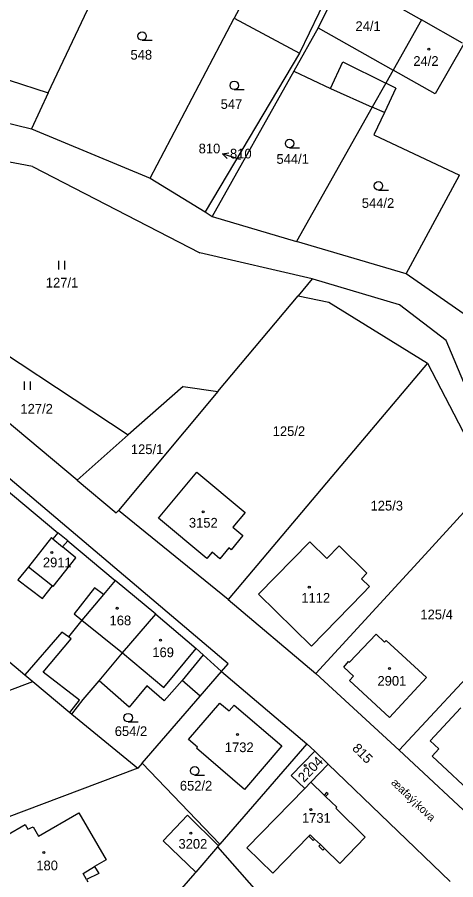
# Model space of a CAD drawing. Extents: x -735249 to -729401, y -1124843 to -1121828.
# Drawn here: x -734491.8 to -734414.9, y -1123251.2 to -1123099.8 of the extents above; entities that cross this region are included whole.
import ezdxf

# ---------------------------------------------------------------- set-up
doc = ezdxf.new("R2010")
doc.units = 0
for name, color, linetype in [('Vrstva 1', 7, 'Continuous'), ('Vrstva 15', 7, 'Continuous'), ('Vrstva 16', 7, 'Continuous'), ('Vrstva 18', 7, 'Continuous'), ('Vrstva 19', 7, 'Continuous'), ('Vrstva 25', 7, 'Continuous'), ('Vrstva 4', 7, 'Continuous')]:
    doc.layers.add(name, color=color, linetype=linetype)

msp = doc.modelspace()

# ---------------------------------------------------------------- linework, layer by layer
at = {"layer": 'Vrstva 1'}
for points in [[(-734486.39, -1123113.07), (-734474.7, -1123088.32)], [(-734435.54, -1123092.02), (-734442.31, -1123106.14)], [(-734434.51, -1123092.58), (-734439.06, -1123101.69)], [(-734434.51, -1123092.58), (-734420.91, -1123100.29)], [(-734452.51, -1123097.58), (-734453.76, -1123099.97)], [(-734468.49, -1123128.05), (-734453.76, -1123099.97)], [(-734453.76, -1123099.97), (-734442.31, -1123106.14)], [(-734439.06, -1123101.69), (-734443.32, -1123109.26)], [(-734420.91, -1123100.29), (-734425.89, -1123109.1)], [(-734413.69, -1123104.39), (-734420.91, -1123100.29)], [(-734442.31, -1123106.14), (-734458.84, -1123133.95)], [(-734500.17, -1123108.63), (-734486.39, -1123113.07)], [(-734443.32, -1123109.26), (-734457.65, -1123134.79)], [(-734443.32, -1123109.26), (-734436.89, -1123112.35)], [(-734425.89, -1123109.1), (-734427.19, -1123111.4)], [(-734427.19, -1123111.4), (-734429.54, -1123115.57)], [(-734486.39, -1123113.07), (-734489.33, -1123119.37)], [(-734436.89, -1123112.35), (-734429.54, -1123115.57)], [(-734504.01, -1123115.82), (-734489.33, -1123119.37)], [(-734429.54, -1123115.57), (-734442.85, -1123139.15)], [(-734427.4, -1123116.52), (-734429.54, -1123115.57)], [(-734427.4, -1123116.52), (-734429.27, -1123120.47)], [(-734489.33, -1123119.37), (-734468.49, -1123128.05)], [(-734429.27, -1123120.47), (-734414.25, -1123127.53)], [(-734489.13, -1123126), (-734505.01, -1123123.05)], [(-734489.13, -1123126), (-734459.78, -1123141.16)], [(-734468.49, -1123128.05), (-734458.84, -1123133.95)], [(-734423.62, -1123144.82), (-734414.25, -1123127.53)], [(-734458.84, -1123133.95), (-734457.65, -1123134.79)], [(-734457.65, -1123134.79), (-734442.85, -1123139.15)], [(-734423.62, -1123144.82), (-734442.85, -1123139.15)], [(-734440.1, -1123145.74), (-734459.78, -1123141.16)], [(-734412.28, -1123152.75), (-734423.62, -1123144.82)], [(-734440.1, -1123145.74), (-734442.57, -1123148.7)], [(-734439.9, -1123145.79), (-734440.1, -1123145.74)], [(-734424.74, -1123150.27), (-734439.9, -1123145.79)], [(-734456.61, -1123165.48), (-734442.57, -1123148.7)], [(-734442.57, -1123148.7), (-734437.16, -1123149.8)], [(-734437.16, -1123149.8), (-734419.85, -1123160.54)], [(-734416.57, -1123156.53), (-734424.74, -1123150.27)], [(-734481.34, -1123181.03), (-734516.02, -1123152.01)], [(-734503.95, -1123152.26), (-734472.39, -1123173.12)], [(-734409.42, -1123173.51), (-734416.57, -1123156.53)], [(-734419.85, -1123160.54), (-734435.04, -1123178.54)], [(-734419.85, -1123160.54), (-734412.87, -1123173.93)], [(-734462.72, -1123164.61), (-734472.39, -1123173.12)], [(-734462.72, -1123164.61), (-734456.61, -1123165.48)], [(-734456.61, -1123165.48), (-734474.07, -1123186.34)], [(-734481.34, -1123181.03), (-734472.39, -1123173.12)], [(-734498.5, -1123178.75), (-734484.68, -1123190.29)], [(-734435.04, -1123178.54), (-734454.83, -1123202.01)], [(-734467.06, -1123187.71), (-734460.3, -1123179.62), (-734451.82, -1123186.7), (-734454.01, -1123189.32), (-734452.26, -1123190.78), (-734454.32, -1123193.25), (-734454.68, -1123192.94), (-734456.26, -1123194.83), (-734457.65, -1123193.67), (-734458.58, -1123194.79), (-734467.06, -1123187.71)], [(-734406.62, -1123179.2), (-734420.92, -1123194.8)], [(-734481.34, -1123181.03), (-734474.45, -1123186.79)], [(-734474.07, -1123186.34), (-734474.45, -1123186.79)], [(-734470.31, -1123189.4), (-734474.07, -1123186.34)], [(-734454.83, -1123202.01), (-734470.31, -1123189.4)], [(-734484.68, -1123190.29), (-734485.56, -1123191.35)], [(-734482.98, -1123191.7), (-734484.68, -1123190.29)], [(-734485.83, -1123191.13), (-734489.88, -1123196.23)], [(-734485.56, -1123191.35), (-734485.83, -1123191.13)], [(-734483.86, -1123192.76), (-734482.98, -1123191.7)], [(-734482.98, -1123191.7), (-734474.65, -1123198.66)], [(-734449.52, -1123201.07), (-734440.51, -1123191.84)], [(-734437.49, -1123194.78), (-734440.51, -1123191.84)], [(-734481.55, -1123194.67), (-734483.86, -1123192.76)], [(-734435.36, -1123192.59), (-734437.49, -1123194.78)], [(-734435.36, -1123192.59), (-734430.49, -1123197.38)], [(-734485.53, -1123199.68), (-734481.55, -1123194.67)], [(-734420.92, -1123194.8), (-734439.44, -1123214.99)], [(-734513.2, -1123196.08), (-734490.49, -1123215.19)], [(-734489.88, -1123196.23), (-734491.7, -1123198.53)], [(-734491.7, -1123198.53), (-734487.39, -1123201.8)], [(-734430.49, -1123197.38), (-734431.44, -1123198.35)], [(-734431.44, -1123198.35), (-734430.04, -1123199.72)], [(-734487.39, -1123201.8), (-734485.64, -1123199.59)], [(-734485.64, -1123199.59), (-734485.53, -1123199.68)], [(-734478.28, -1123199.95), (-734481.85, -1123204.5)], [(-734476.7, -1123201.1), (-734478.28, -1123199.95)], [(-734474.65, -1123198.66), (-734476.7, -1123201.1)], [(-734467.53, -1123204.57), (-734474.65, -1123198.66)], [(-734430.04, -1123199.72), (-734431.21, -1123200.92)], [(-734440.22, -1123210.15), (-734449.52, -1123201.07)], [(-734431.21, -1123200.92), (-734440.22, -1123210.15)], [(-734454.83, -1123202.01), (-734439.44, -1123214.99)], [(-734481.85, -1123204.5), (-734480.49, -1123205.6)], [(-734473.34, -1123211.37), (-734467.53, -1123204.57)], [(-734467.53, -1123204.57), (-734460.43, -1123210.59)], [(-734480.49, -1123205.6), (-734482.86, -1123208.54)], [(-734483.99, -1123207.72), (-734490.49, -1123215.19)], [(-734482.86, -1123208.54), (-734483.99, -1123207.72)], [(-734433.56, -1123213), (-734428.87, -1123208.08)], [(-734428.87, -1123208.08), (-734427.38, -1123209.46)], [(-734460.43, -1123210.59), (-734459.22, -1123211.69)], [(-734427.38, -1123209.46), (-734427.11, -1123209.16)], [(-734427.11, -1123209.16), (-734420.02, -1123215.66)], [(-734477.48, -1123216.25), (-734473.34, -1123211.37)], [(-734459.22, -1123211.69), (-734456.01, -1123214.6)], [(-734408.37, -1123210.75), (-734424.82, -1123228.4)], [(-734434.51, -1123213.85), (-734433.7, -1123212.88)], [(-734433.7, -1123212.88), (-734433.56, -1123213)], [(-734490.49, -1123215.19), (-734489.08, -1123216.38)], [(-734459.76, -1123218.94), (-734456.01, -1123214.6)], [(-734456.01, -1123214.6), (-734441, -1123227.32)], [(-734424.82, -1123228.4), (-734439.44, -1123214.99)], [(-734432.86, -1123215.43), (-734434.51, -1123213.85)], [(-734514.75, -1123226.02), (-734489.08, -1123216.38)], [(-734489.08, -1123216.38), (-734482.61, -1123221.83)], [(-734480.26, -1123219.52), (-734477.48, -1123216.25)], [(-734472.2, -1123220.87), (-734477.48, -1123216.25)], [(-734462.9, -1123216.22), (-734466.05, -1123219.77)], [(-734459.76, -1123218.94), (-734462.9, -1123216.22)], [(-734433.56, -1123216.2), (-734432.86, -1123215.43)], [(-734426.5, -1123222.7), (-734433.56, -1123216.2)], [(-734420.02, -1123215.66), (-734426.5, -1123222.7)], [(-734469.09, -1123217.11), (-734472.2, -1123220.87)], [(-734466.05, -1123219.77), (-734469.09, -1123217.11)], [(-734482.25, -1123222.13), (-734480.26, -1123219.52)], [(-734469.9, -1123230.68), (-734459.76, -1123218.94)], [(-734461.77, -1123226.54), (-734456.29, -1123220.15)], [(-734456.29, -1123220.15), (-734454.66, -1123221.54)], [(-734454.66, -1123221.54), (-734453.79, -1123220.53)], [(-734453.79, -1123220.53), (-734445.43, -1123227.69)], [(-734419.38, -1123226.8), (-734413.99, -1123221.02)], [(-734482.61, -1123221.83), (-734482.25, -1123222.13)], [(-734482.25, -1123222.13), (-734470.68, -1123231.58)], [(-734460.19, -1123227.89), (-734461.77, -1123226.54)], [(-734417.88, -1123228.2), (-734419.38, -1123226.8)], [(-734460.37, -1123228.09), (-734460.19, -1123227.89)], [(-734451.95, -1123235.3), (-734460.37, -1123228.09)], [(-734441, -1123227.32), (-734456.28, -1123244.9)], [(-734445.43, -1123227.69), (-734451.95, -1123235.3)], [(-734443.76, -1123232.84), (-734439.64, -1123228.57)], [(-734439.64, -1123228.57), (-734441, -1123227.32)], [(-734437.26, -1123230.89), (-734439.64, -1123228.57)], [(-734410.13, -1123242.09), (-734424.82, -1123228.4)], [(-734419.06, -1123229.47), (-734417.88, -1123228.2)], [(-734411.03, -1123236.99), (-734419.06, -1123229.47)], [(-734470.68, -1123231.58), (-734507.19, -1123245.31)], [(-734469.9, -1123230.68), (-734470.68, -1123231.58)], [(-734456.28, -1123244.9), (-734469.9, -1123230.68)], [(-734440.31, -1123234.02), (-734437.26, -1123230.89)], [(-734415.86, -1123251.49), (-734437.26, -1123230.89)], [(-734441.4, -1123235.14), (-734443.76, -1123232.84)], [(-734440.31, -1123234.02), (-734441.4, -1123235.14)], [(-734437.97, -1123236.29), (-734440.31, -1123234.02)], [(-734441.4, -1123235.14), (-734451.54, -1123245.57)], [(-734437.55, -1123235.85), (-734437.97, -1123236.29)], [(-734437.72, -1123236.53), (-734437.29, -1123236.1)], [(-734437.29, -1123236.1), (-734437.55, -1123235.85)], [(-734435.75, -1123238.44), (-734437.72, -1123236.53)], [(-734488.1, -1123243.51), (-734481.02, -1123239.42)], [(-734481.02, -1123239.42), (-734476.25, -1123247.68)], [(-734435.92, -1123238.62), (-734435.75, -1123238.44)], [(-734430.81, -1123243.7), (-734435.92, -1123238.62)], [(-734466.25, -1123244.32), (-734461.94, -1123239.83)], [(-734461.94, -1123239.83), (-734456.51, -1123245.2)], [(-734493.65, -1123243.33), (-734490.42, -1123241.45)], [(-734490.42, -1123241.45), (-734489.94, -1123242.28)], [(-734489.94, -1123242.28), (-734489.06, -1123241.85)], [(-734489.06, -1123241.85), (-734488.1, -1123243.51)], [(-734446.98, -1123250), (-734440.7, -1123243.54)], [(-734440.7, -1123243.54), (-734439.93, -1123244.29)], [(-734435.22, -1123248.31), (-734430.81, -1123243.7)], [(-734460.51, -1123249.82), (-734466.25, -1123244.32)], [(-734456.67, -1123245.41), (-734460.51, -1123249.82)], [(-734456.51, -1123245.2), (-734456.67, -1123245.41)], [(-734456.67, -1123245.41), (-734447.26, -1123256.1)], [(-734456.51, -1123245.2), (-734456.28, -1123244.9)], [(-734439.93, -1123244.29), (-734439.65, -1123244.01)], [(-734439.65, -1123244.01), (-734438.62, -1123245)], [(-734438.62, -1123245), (-734438.9, -1123245.29)], [(-734438.9, -1123245.29), (-734438.19, -1123245.98)], [(-734451.54, -1123245.57), (-734446.98, -1123250)], [(-734438.19, -1123245.98), (-734437.91, -1123245.69)], [(-734437.91, -1123245.69), (-734435.22, -1123248.31)], [(-734476.25, -1123247.68), (-734478.25, -1123248.86)], [(-734478.25, -1123248.86), (-734477.52, -1123250.08)], [(-734460.68, -1123250.01), (-734472.8, -1123263.91)], [(-734460.68, -1123250.01), (-734460.51, -1123249.82)], [(-734477.52, -1123250.08), (-734479.67, -1123251.13)], [(-734479.67, -1123251.13), (-734479.42, -1123251.55)]]:
    msp.add_lwpolyline(points, dxfattribs=at)
at = {"layer": 'Vrstva 16'}
msp.add_lwpolyline([(-734452.68, -1123124.8), (-734452.94, -1123124.72)], dxfattribs=at)
at = {"layer": 'Vrstva 25'}
for points in [[(-734469.93, -1123103.87), (-734468.18, -1123103.87)], [(-734453.75, -1123112.52), (-734452, -1123112.52)], [(-734444.04, -1123122.72), (-734442.29, -1123122.72)], [(-734454.997, -1123124.589), (-734455.797, -1123123.808), (-734454.693, -1123123.636)], [(-734452.94, -1123124.72), (-734455.797, -1123123.808)], [(-734428.47, -1123130.16), (-734426.72, -1123130.16)], [(-734484.517, -1123144.065), (-734484.517, -1123142.565)], [(-734483.483, -1123144.065), (-734483.483, -1123142.565)], [(-734490.537, -1123165.205), (-734490.537, -1123163.705)], [(-734489.503, -1123165.205), (-734489.503, -1123163.705)], [(-734472.38, -1123223.47), (-734470.63, -1123223.47)], [(-734460.7, -1123232.78), (-734458.95, -1123232.78)]]:
    msp.add_lwpolyline(points, dxfattribs=at)
for centre, radius in [((-734469.93, -1123103.12), 0.75), ((-734419.63, -1123105.44), 0.175), ((-734453.75, -1123111.77), 0.75), ((-734444.04, -1123121.97), 0.75), ((-734428.47, -1123129.41), 0.75), ((-734459.19, -1123186.62), 0.175), ((-734485.75, -1123193.73), 0.175), ((-734440.59, -1123199.83), 0.175), ((-734474.31, -1123203.53), 0.175), ((-734466.68, -1123209.12), 0.175), ((-734426.52, -1123214.1), 0.175), ((-734472.38, -1123222.72), 0.75), ((-734453.2, -1123225.66), 0.175), ((-734460.7, -1123232.03), 0.75), ((-734441.33, -1123231.1), 0.175), ((-734440.33, -1123238.86), 0.175), ((-734461.38, -1123242.97), 0.175), ((-734487.15, -1123246.39), 0.175)]:
    msp.add_circle(centre, radius, dxfattribs=at)
at = {"layer": 'Vrstva 4'}
for points in [[(-734439.06, -1123101.69), (-734425.89, -1123109.1)], [(-734413.47, -1123104.51), (-734418.48, -1123113.27)], [(-734436.89, -1123112.35), (-734434.69, -1123107.67)], [(-734434.69, -1123107.67), (-734427.19, -1123111.4)], [(-734418.48, -1123113.27), (-734425.89, -1123109.1)], [(-734425.4, -1123112.29), (-734427.4, -1123116.52)], [(-734425.4, -1123112.29), (-734427.19, -1123111.4)], [(-734454.81, -1123213.28), (-734531.79, -1123148.14)], [(-734485.56, -1123191.35), (-734483.86, -1123192.76)], [(-734489.88, -1123196.23), (-734485.64, -1123199.59)], [(-734476.7, -1123201.1), (-734480.49, -1123205.6)], [(-734480.49, -1123205.6), (-734473.34, -1123211.37)], [(-734487.28, -1123214.76), (-734482.39, -1123208.88)], [(-734482.39, -1123208.88), (-734482.86, -1123208.54)], [(-734466.13, -1123217.43), (-734460.43, -1123210.59)], [(-734473.34, -1123211.37), (-734466.13, -1123217.43)], [(-734459.22, -1123211.69), (-734462.9, -1123216.22)], [(-734456.01, -1123214.6), (-734454.81, -1123213.28)], [(-734480.93, -1123219.63), (-734487.28, -1123214.76)], [(-734482.61, -1123221.83), (-734480.93, -1123219.63)], [(-734437.97, -1123236.29), (-734437.72, -1123236.53)], [(-734440.7, -1123243.54), (-734440.42, -1123243.25)], [(-734440.42, -1123243.25), (-734439.65, -1123244.01)], [(-734438.62, -1123245), (-734437.91, -1123245.69)], [(-734480.29, -1123250.07), (-734478.25, -1123248.86)], [(-734479.67, -1123251.13), (-734480.29, -1123250.07)]]:
    msp.add_lwpolyline(points, dxfattribs=at)

# ---------------------------------------------------------------- texts
at = {"layer": 'Vrstva 15'}
msp.add_text('æafaý¡kova', height=1.4, rotation=316.20251, dxfattribs=at).set_placement((-734426.318, -1123234.265))
at = {"layer": 'Vrstva 16'}
msp.add_text('810', height=1.7, dxfattribs=at).set_placement((-734460.003, -1123123.7))
at = {"layer": 'Vrstva 18'}
for s, p in [('548', (-734471.96, -1123107.25)), ('547', (-734456.14, -1123115.9)), ('810', (-734454.503, -1123124.6)), ('544/1', (-734446.35, -1123125.54)), ('544/2', (-734431.38, -1123133.27)), ('127/1', (-734486.81, -1123147.24)), ('127/2', (-734491.27, -1123169.37)), ('125/2', (-734447.01, -1123173.3)), ('125/1', (-734471.89, -1123176.47)), ('125/3', (-734429.84, -1123186.37)), ('125/4', (-734421.1, -1123205.46)), ('654/2', (-734474.72, -1123225.94)), ('652/2', (-734463.3, -1123235.51))]:
    msp.add_text(s, height=1.7, dxfattribs=at).set_placement(p)
msp.add_text('815', height=1.7, rotation=315.00251, dxfattribs=at).set_placement((-734433.178, -1123228.24))
at = {"layer": 'Vrstva 19'}
for s, p in [('24/1', (-734432.49, -1123102.23)), ('24/2', (-734422.34, -1123108.35)), ('3152', (-734461.713, -1123189.37)), ('2911', (-734487.33, -1123196.33)), ('1112', (-734441.99, -1123202.54)), ('168', (-734475.63, -1123206.51)), ('169', (-734468.13, -1123212.1)), ('2901', (-734428.63, -1123217.11)), ('1732', (-734455.41, -1123228.77)), ('1731', (-734441.88, -1123241.17)), ('3202', (-734463.543, -1123245.71)), ('180', (-734488.48, -1123249.5))]:
    msp.add_text(s, height=1.7, dxfattribs=at).set_placement(p)
msp.add_text('2204', height=1.7, rotation=46.10037, dxfattribs=at).set_placement((-734441.535, -1123234.178))

doc.saveas('drawing.dxf')
